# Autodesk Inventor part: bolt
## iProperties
Created: 2009-04
Part Number: bolt
Document SubType Name: Modeling
Designer: Sham
Density: 1 g/cm^3
Author: Sham
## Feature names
1. Extrusion1
2. Extrusion2
3. Extrusion3
4. Chamfer1
